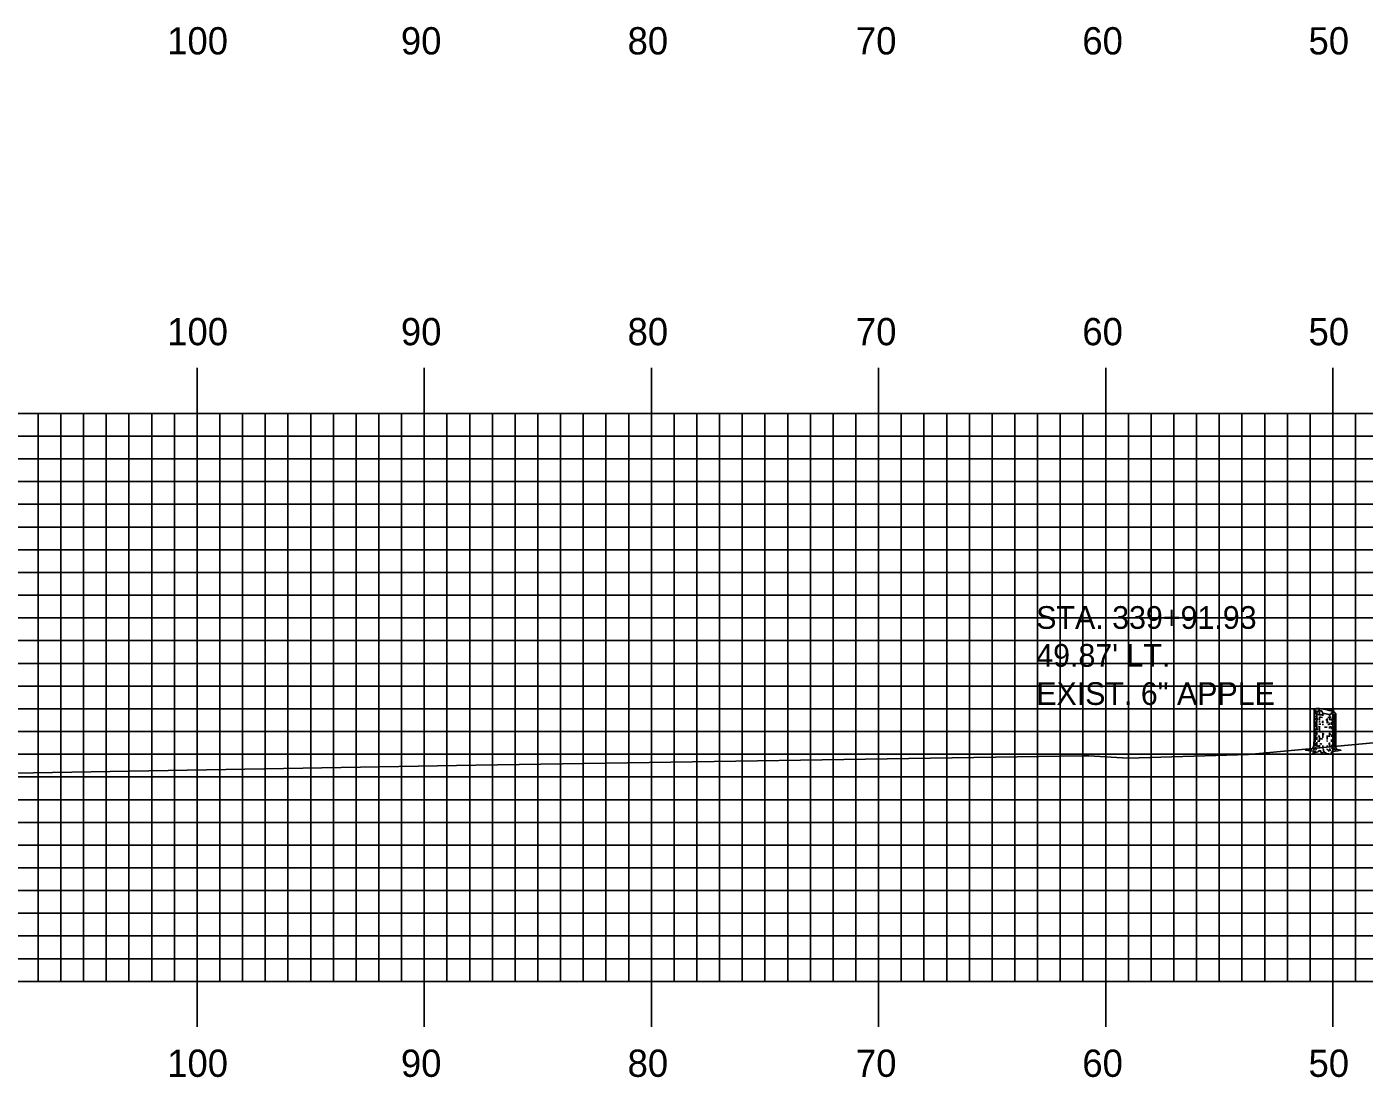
# Model space of a CAD drawing. Extents: x 1824360 to 1824703, y 442591 to 442811.
# Drawn here: x 1824417.8 to 1824476.7, y 442699.4 to 442745.7 of the extents above; entities that cross this region are included whole.
import ezdxf

# ---------------------------------------------------------------- set-up
doc = ezdxf.new("R2010")
doc.units = 0
for name, color, linetype in [('D_Text_Monospaced', 7, 'Continuous'), ('H_V ANNOTATION', 7, 'Continuous'), ('MAJOR', 7, 'Continuous'), ('MINOR', 7, 'Continuous'), ('S_Roadway_Centerline', 7, 'Continuous'), ('S_Trees_Decid_NonPay', 7, 'Continuous')]:
    doc.layers.add(name, color=color, linetype=linetype)

msp = doc.modelspace()

# ---------------------------------------------------------------- linework, layer by layer
at = {"layer": 'MAJOR'}
for p, q in [((1824425.335, 442730.669), (1824425.335, 442728.665)), ((1824435.335, 442730.669), (1824435.335, 442728.665)), ((1824445.335, 442730.669), (1824445.335, 442728.665)), ((1824455.335, 442730.669), (1824455.335, 442728.665)), ((1824465.335, 442730.669), (1824465.335, 442728.665)), ((1824475.335, 442730.669), (1824475.335, 442728.665)), ((1824385.335, 442728.665), (1824665.335, 442728.665)), ((1824385.335, 442728.665), (1824665.335, 442728.665)), ((1824425.335, 442703.665), (1824425.335, 442728.665)), ((1824435.335, 442703.665), (1824435.335, 442728.665)), ((1824445.335, 442703.665), (1824445.335, 442728.665)), ((1824455.335, 442703.665), (1824455.335, 442728.665)), ((1824465.335, 442703.665), (1824465.335, 442728.665)), ((1824475.335, 442703.665), (1824475.335, 442728.665)), ((1824385.335, 442723.665), (1824665.335, 442723.665)), ((1824385.335, 442718.665), (1824665.335, 442718.665)), ((1824385.335, 442713.665), (1824665.335, 442713.665)), ((1824385.335, 442708.665), (1824665.335, 442708.665)), ((1824385.335, 442703.665), (1824665.335, 442703.665)), ((1824385.335, 442703.665), (1824665.335, 442703.665)), ((1824425.335, 442701.661), (1824425.335, 442703.665)), ((1824435.335, 442701.661), (1824435.335, 442703.665)), ((1824445.335, 442701.661), (1824445.335, 442703.665)), ((1824455.335, 442701.661), (1824455.335, 442703.665)), ((1824465.335, 442701.661), (1824465.335, 442703.665)), ((1824475.335, 442701.661), (1824475.335, 442703.665))]:
    msp.add_line(p, q, dxfattribs=at)
at = {"layer": 'MINOR'}
for p, q in [((1824418.335, 442703.665), (1824418.335, 442728.665)), ((1824419.335, 442703.665), (1824419.335, 442728.665)), ((1824420.335, 442703.665), (1824420.335, 442728.665)), ((1824421.335, 442703.665), (1824421.335, 442728.665)), ((1824422.335, 442703.665), (1824422.335, 442728.665)), ((1824423.335, 442703.665), (1824423.335, 442728.665)), ((1824424.335, 442703.665), (1824424.335, 442728.665)), ((1824426.335, 442703.665), (1824426.335, 442728.665)), ((1824427.335, 442703.665), (1824427.335, 442728.665)), ((1824428.335, 442703.665), (1824428.335, 442728.665)), ((1824429.335, 442703.665), (1824429.335, 442728.665)), ((1824430.335, 442703.665), (1824430.335, 442728.665)), ((1824431.335, 442703.665), (1824431.335, 442728.665)), ((1824432.335, 442703.665), (1824432.335, 442728.665)), ((1824433.335, 442703.665), (1824433.335, 442728.665)), ((1824434.335, 442703.665), (1824434.335, 442728.665)), ((1824436.335, 442703.665), (1824436.335, 442728.665)), ((1824437.335, 442703.665), (1824437.335, 442728.665)), ((1824438.335, 442703.665), (1824438.335, 442728.665)), ((1824439.335, 442703.665), (1824439.335, 442728.665)), ((1824440.335, 442703.665), (1824440.335, 442728.665)), ((1824441.335, 442703.665), (1824441.335, 442728.665)), ((1824442.335, 442703.665), (1824442.335, 442728.665)), ((1824443.335, 442703.665), (1824443.335, 442728.665)), ((1824444.335, 442703.665), (1824444.335, 442728.665)), ((1824446.335, 442703.665), (1824446.335, 442728.665)), ((1824447.335, 442703.665), (1824447.335, 442728.665)), ((1824448.335, 442703.665), (1824448.335, 442728.665)), ((1824449.335, 442703.665), (1824449.335, 442728.665)), ((1824450.335, 442703.665), (1824450.335, 442728.665)), ((1824451.335, 442703.665), (1824451.335, 442728.665)), ((1824452.335, 442703.665), (1824452.335, 442728.665)), ((1824453.335, 442703.665), (1824453.335, 442728.665)), ((1824454.335, 442703.665), (1824454.335, 442728.665)), ((1824456.335, 442703.665), (1824456.335, 442728.665)), ((1824457.335, 442703.665), (1824457.335, 442728.665)), ((1824458.335, 442703.665), (1824458.335, 442728.665)), ((1824459.335, 442703.665), (1824459.335, 442728.665)), ((1824460.335, 442703.665), (1824460.335, 442728.665)), ((1824461.335, 442703.665), (1824461.335, 442728.665)), ((1824462.335, 442703.665), (1824462.335, 442728.665)), ((1824463.335, 442703.665), (1824463.335, 442728.665)), ((1824464.335, 442703.665), (1824464.335, 442728.665)), ((1824466.335, 442703.665), (1824466.335, 442728.665)), ((1824467.335, 442703.665), (1824467.335, 442728.665)), ((1824468.335, 442703.665), (1824468.335, 442728.665)), ((1824469.335, 442703.665), (1824469.335, 442728.665)), ((1824470.335, 442703.665), (1824470.335, 442728.665)), ((1824471.335, 442703.665), (1824471.335, 442728.665)), ((1824472.335, 442703.665), (1824472.335, 442728.665)), ((1824473.335, 442703.665), (1824473.335, 442728.665)), ((1824474.335, 442703.665), (1824474.335, 442728.665)), ((1824476.335, 442703.665), (1824476.335, 442728.665)), ((1824385.335, 442727.665), (1824665.335, 442727.665)), ((1824385.335, 442726.665), (1824665.335, 442726.665)), ((1824385.335, 442725.665), (1824665.335, 442725.665)), ((1824385.335, 442724.665), (1824665.335, 442724.665)), ((1824385.335, 442722.665), (1824665.335, 442722.665)), ((1824385.335, 442721.665), (1824665.335, 442721.665)), ((1824385.335, 442720.665), (1824665.335, 442720.665)), ((1824385.335, 442719.665), (1824665.335, 442719.665)), ((1824385.335, 442717.665), (1824665.335, 442717.665)), ((1824385.335, 442716.665), (1824665.335, 442716.665)), ((1824385.335, 442715.665), (1824665.335, 442715.665)), ((1824385.335, 442714.665), (1824665.335, 442714.665)), ((1824385.335, 442712.665), (1824665.335, 442712.665)), ((1824385.335, 442711.665), (1824665.335, 442711.665)), ((1824385.335, 442710.665), (1824665.335, 442710.665)), ((1824385.335, 442709.665), (1824665.335, 442709.665)), ((1824385.335, 442707.665), (1824665.335, 442707.665)), ((1824385.335, 442706.665), (1824665.335, 442706.665)), ((1824385.335, 442705.665), (1824665.335, 442705.665)), ((1824385.335, 442704.665), (1824665.335, 442704.665))]:
    msp.add_line(p, q, dxfattribs=at)
at = {"layer": 'S_Roadway_Centerline'}
msp.add_lwpolyline([(1824385.335, 442712.032), (1824402.824, 442712.451), (1824409.16, 442712.566), (1824410.669, 442712.679), (1824412.52, 442712.735), (1824413.871, 442712.78), (1824437.612, 442713.181), (1824464.293, 442713.588), (1824464.596, 442713.6), (1824466.327, 442713.494), (1824471.624, 442713.647), (1824477.578, 442714.207)], dxfattribs=at)
at = {"layer": 'S_Trees_Decid_NonPay'}
for p, q in [((1824474.564, 442715.583), (1824474.564, 442715.488)), ((1824474.564, 442715.262), (1824474.564, 442715.179)), ((1824474.564, 442715.109), (1824474.564, 442714.858)), ((1824474.632, 442715.496), (1824474.632, 442715.195)), ((1824474.632, 442715.167), (1824474.632, 442715.035)), ((1824474.632, 442715.001), (1824474.632, 442714.72)), ((1824474.751, 442715.513), (1824474.751, 442715.365)), ((1824474.751, 442715.317), (1824474.751, 442715.148)), ((1824474.898, 442715.467), (1824474.898, 442715.36)), ((1824474.898, 442715.132), (1824474.898, 442715.045)), ((1824474.898, 442715.01), (1824474.898, 442714.94)), ((1824475.078, 442715.231), (1824475.078, 442715.031)), ((1824475.195, 442715.415), (1824475.195, 442715.336)), ((1824475.195, 442715.249), (1824475.195, 442715.165)), ((1824475.195, 442715.054), (1824475.195, 442714.953)), ((1824475.282, 442715.231), (1824475.282, 442715.144)), ((1824475.282, 442715.074), (1824475.282, 442714.953)), ((1824475.353, 442715.404), (1824475.353, 442715.352)), ((1824475.353, 442715.249), (1824475.353, 442715.167)), ((1824475.353, 442715.132), (1824475.353, 442715.058)), ((1824475.353, 442715.031), (1824475.353, 442714.971)), ((1824475.395, 442715.409), (1824475.395, 442715.191)), ((1824475.395, 442715.123), (1824475.395, 442714.971)), ((1824475.422, 442715.339), (1824475.422, 442715.257)), ((1824475.422, 442715.188), (1824475.422, 442715.058)), ((1824475.422, 442715.035), (1824475.422, 442714.854)), ((1824474.564, 442714.775), (1824474.564, 442714.545)), ((1824474.564, 442714.475), (1824474.564, 442714.314)), ((1824474.632, 442714.65), (1824474.632, 442714.506)), ((1824474.632, 442714.436), (1824474.632, 442714.294)), ((1824474.751, 442714.842), (1824474.751, 442714.693)), ((1824474.751, 442714.424), (1824474.751, 442714.271)), ((1824474.898, 442714.607), (1824474.898, 442714.384)), ((1824475.078, 442714.493), (1824475.078, 442714.306)), ((1824475.195, 442714.868), (1824475.195, 442714.792)), ((1824475.195, 442714.607), (1824475.195, 442714.51)), ((1824475.282, 442714.877), (1824475.282, 442714.763)), ((1824475.282, 442714.701), (1824475.282, 442714.619)), ((1824475.282, 442714.533), (1824475.282, 442714.436)), ((1824475.353, 442714.918), (1824475.353, 442714.737)), ((1824475.353, 442714.705), (1824475.353, 442714.623)), ((1824475.353, 442714.569), (1824475.353, 442714.399)), ((1824475.353, 442714.365), (1824475.353, 442714.086)), ((1824475.395, 442714.866), (1824475.395, 442714.788)), ((1824475.395, 442714.761), (1824475.395, 442714.654)), ((1824475.395, 442714.619), (1824475.395, 442714.518)), ((1824475.395, 442714.493), (1824475.395, 442714.31)), ((1824475.422, 442714.806), (1824475.422, 442714.56)), ((1824475.422, 442714.541), (1824475.422, 442714.446)), ((1824475.424, 442714.393), (1824475.423, 442714.133)), ((1824474.564, 442714.298), (1824474.564, 442714.193)), ((1824474.564, 442714.156), (1824474.564, 442714.032)), ((1824474.631, 442713.952), (1824474.59, 442713.856)), ((1824474.632, 442714.193), (1824474.632, 442714.012)), ((1824474.751, 442714.059), (1824474.751, 442713.981)), ((1824474.898, 442714.051), (1824474.898, 442713.985)), ((1824474.938, 442713.765), (1824474.903, 442713.911)), ((1824475.078, 442714.275), (1824475.078, 442714.222)), ((1824475.078, 442714.046), (1824475.078, 442713.956)), ((1824475.195, 442714.185), (1824475.195, 442713.961)), ((1824475.282, 442714.306), (1824475.282, 442714.207)), ((1824475.282, 442714.078), (1824475.282, 442714.02)), ((1824475.353, 442714.033), (1824475.353, 442714.008)), ((1824475.393, 442713.968), (1824475.428, 442713.917)), ((1824475.395, 442714.207), (1824475.395, 442714.016)), ((1824475.475, 442713.847), (1824475.408, 442713.878)), ((1824475.422, 442714.094), (1824475.422, 442714.02))]:
    msp.add_line(p, q, dxfattribs=at)
for points in [[(1824475.463, 442715.447), (1824475.463, 442714.035), (1824475.486, 442713.886), (1824475.689, 442713.843), (1824475.549, 442713.808), (1824475.331, 442713.789), (1824475.261, 442713.746), (1824475.383, 442713.657), (1824475.051, 442713.701), (1824474.938, 442713.765), (1824474.845, 442713.705), (1824474.79, 442713.783), (1824474.798, 442713.82), (1824474.736, 442713.822), (1824474.685, 442713.765), (1824474.452, 442713.713), (1824474.58, 442713.802), (1824474.448, 442713.804), (1824474.139, 442713.841), (1824474.378, 442713.872), (1824474.456, 442713.93), (1824474.495, 442714.051), (1824474.512, 442714.405), (1824474.512, 442715.638)], [(1824474.876, 442715.472), (1824474.868, 442715.539), (1824474.843, 442715.544), (1824474.835, 442715.579), (1824474.804, 442715.564), (1824474.79, 442715.579), (1824474.765, 442715.556), (1824474.742, 442715.564), (1824474.73, 442715.613), (1824474.722, 442715.57), (1824474.691, 442715.579), (1824474.688, 442715.527)], [(1824475.368, 442715.527), (1824475.364, 442715.622), (1824475.35, 442715.595), (1824475.35, 442715.716), (1824475.329, 442715.653), (1824475.314, 442715.686), (1824475.298, 442715.63), (1824475.282, 442715.647), (1824475.263, 442715.638), (1824475.244, 442715.571)], [(1824475.346, 442715.403), (1824475.329, 442715.465), (1824475.307, 442715.453), (1824475.276, 442715.488), (1824475.242, 442715.41)], [(1824474.561, 442713.989), (1824474.553, 442713.913), (1824474.475, 442713.863)], [(1824475.086, 442713.907), (1824475.086, 442713.87), (1824475.137, 442713.839), (1824475.154, 442713.789)], [(1824475.198, 442713.913), (1824475.204, 442713.843), (1824475.267, 442713.831)], [(1824475.345, 442713.878), (1824475.302, 442713.913), (1824475.294, 442713.961)], [(1824475.424, 442713.894), (1824475.345, 442713.878), (1824475.329, 442713.835)]]:
    msp.add_lwpolyline(points, dxfattribs=at)
for centre, radius, start, end in [((1824474.53, 442715.638), 0.0179, 168.17229, 184.22782), ((1824474.536, 442715.639), 0.0237, 184.22782, 198.17229), ((1824474.53, 442715.638), 0.0179, 152.11676, 168.17229), ((1824474.545, 442715.642), 0.0336, 198.17229, 216.94859), ((1824474.535, 442715.636), 0.0237, 138.17229, 152.11676), ((1824474.543, 442715.629), 0.0336, 119.39599, 138.17229), ((1824474.593, 442715.678), 0.0935, 216.9486, 228.17229), ((1824474.572, 442715.577), 0.0935, 108.17229, 119.39599), ((1824474.745, 442715.848), 0.322, 228.17229, 250.29024), ((1824474.643, 442715.36), 0.322, 86.05435, 108.17229), ((1824475.482, 442717.905), 2.507, 250.29024, 251.52809), ((1824474.493, 442713.18), 2.507, 78.17229, 86.05435), ((1824474.493, 442713.18), 2.507, 70.29024, 78.17229), ((1824475.23, 442715.237), 0.322, 48.17229, 70.29024), ((1824474.531, 442715.491), 0.0191, 163.94846, 180), ((1824474.531, 442715.491), 0.0191, 180, 196.05154), ((1824474.536, 442715.493), 0.0252, 196.05154, 210), ((1824474.531, 442715.277), 0.0191, 163.94846, 180), ((1824474.531, 442715.277), 0.0191, 180, 196.05154), ((1824474.536, 442715.279), 0.0252, 196.05154, 210), ((1824474.531, 442715.174), 0.0191, 163.94846, 180), ((1824474.531, 442715.174), 0.0191, 180, 196.05154), ((1824474.536, 442715.176), 0.0252, 196.05154, 210), ((1824474.531, 442714.954), 0.0191, 163.94846, 180), ((1824474.531, 442714.954), 0.0191, 180, 196.05154), ((1824474.536, 442714.956), 0.0252, 196.05154, 210), ((1824474.546, 442715.498), 0.0356, 210, 228.74941), ((1824474.546, 442715.284), 0.0356, 210, 228.74941), ((1824474.546, 442715.181), 0.0356, 210, 228.74941), ((1824474.546, 442714.961), 0.0356, 210, 228.74941), ((1824474.587, 442715.545), 0.0984, 228.74941, 240), ((1824474.587, 442715.331), 0.0984, 228.74941, 240), ((1824474.587, 442715.228), 0.0984, 228.74941, 240), ((1824474.701, 442715.742), 0.326, 240, 248.32432), ((1824474.701, 442715.528), 0.326, 240, 243.57187), ((1824474.701, 442715.425), 0.326, 240, 243.24303), ((1824474.701, 442715.629), 0.326, 240.90989, 257.8036), ((1824474.701, 442715.32), 0.326, 245.15448, 257.8036), ((1824474.701, 442715.528), 0.326, 250.41675, 261.8968), ((1824474.701, 442715.425), 0.326, 251.68306, 257.8036), ((1824474.701, 442715.742), 0.326, 257.8036, 261.8968), ((1824474.987, 442717.752), 2.356, 261.8968, 263.27991), ((1824474.987, 442717.538), 2.356, 261.8968, 262.55191), ((1824474.987, 442717.33), 2.356, 263.26817, 265.63617), ((1824474.987, 442717.435), 2.356, 263.34129, 264.99462), ((1824474.987, 442717.639), 2.356, 264.24201, 267.36728), ((1824474.987, 442717.752), 2.356, 265.24001, 267.83857), ((1824474.987, 442717.435), 2.356, 266.50356, 267.83857), ((1824475.482, 442717.905), 2.507, 255.99867, 258.17229), ((1824475.482, 442717.905), 2.507, 258.17229, 264.50134), ((1824474.987, 442717.538), 2.356, 270.81188, 272.1981), ((1824474.987, 442717.435), 2.356, 272.1981, 273.97408), ((1824474.987, 442717.33), 2.356, 273.0067, 275.06467), ((1824474.987, 442717.639), 2.356, 273.14807, 276.77338), ((1824474.987, 442717.538), 2.356, 275.06468, 278.1032), ((1824474.987, 442717.33), 2.356, 277.18685, 278.1032), ((1824474.987, 442717.435), 2.356, 277.38384, 278.1032), ((1824475.273, 442715.528), 0.326, 278.1032, 279.08543), ((1824475.273, 442715.425), 0.326, 278.1032, 284.03823), ((1824475.273, 442715.32), 0.326, 278.1032, 284.03823), ((1824475.332, 442715.725), 0.322, 272.44787, 288.17229), ((1824475.273, 442715.629), 0.326, 291.95057, 300), ((1824475.273, 442715.528), 0.326, 291.95057, 300), ((1824475.273, 442715.32), 0.326, 291.95057, 300), ((1824475.403, 442715.508), 0.0935, 288.17229, 299.39599), ((1824475.387, 442715.432), 0.0984, 300, 311.25059), ((1824475.387, 442715.331), 0.0984, 300, 311.25059), ((1824475.387, 442715.123), 0.0984, 300, 311.25059), ((1824475.382, 442715.407), 0.0935, 36.9486, 48.17229), ((1824475.433, 442715.456), 0.0336, 299.39599, 318.17229), ((1824475.428, 442715.385), 0.0356, 311.25059, 330), ((1824475.428, 442715.284), 0.0356, 311.25059, 330), ((1824475.428, 442715.076), 0.0356, 311.25059, 330), ((1824475.428, 442714.961), 0.0356, 311.25059, 330), ((1824475.43, 442715.443), 0.0336, 18.17229, 36.94859), ((1824475.44, 442715.45), 0.0237, 318.17229, 332.11676), ((1824475.437, 442715.379), 0.0252, 330, 343.94846), ((1824475.437, 442715.279), 0.0252, 330, 343.94846), ((1824475.437, 442715.071), 0.0252, 330, 343.94846), ((1824475.437, 442714.956), 0.0252, 330, 343.94846), ((1824475.445, 442715.447), 0.0179, 332.11676, 348.17229), ((1824475.439, 442715.446), 0.0237, 4.22782, 18.17229), ((1824475.443, 442715.378), 0.0191, 360, 6.11276), ((1824475.443, 442715.378), 0.0191, 343.94846, 360), ((1824475.443, 442715.277), 0.0191, 360, 6.11276), ((1824475.443, 442715.277), 0.0191, 343.94846, 360), ((1824475.443, 442715.174), 0.0191, 360, 6.11276), ((1824475.443, 442715.174), 0.0191, 343.94846, 360), ((1824475.443, 442715.069), 0.0191, 360, 6.11276), ((1824475.443, 442715.069), 0.0191, 343.94846, 360), ((1824475.443, 442714.954), 0.0191, 360, 6.11276), ((1824475.443, 442714.954), 0.0191, 343.94846, 360), ((1824475.445, 442715.447), 0.0179, 348.17229, 4.22783), ((1824474.528, 442714.739), 0.0191, 163.94846, 180), ((1824474.531, 442714.839), 0.0191, 163.94846, 180), ((1824474.531, 442714.839), 0.0191, 180, 196.05154), ((1824474.531, 442714.634), 0.0191, 163.94846, 180), ((1824474.531, 442714.634), 0.0191, 180, 196.05154), ((1824474.536, 442714.636), 0.0252, 196.05154, 210), ((1824474.537, 442714.841), 0.0252, 196.05154, 210), ((1824474.546, 442714.846), 0.0356, 210, 228.74941), ((1824474.546, 442714.641), 0.0356, 210, 228.74941), ((1824474.587, 442715.008), 0.0984, 228.74941, 240), ((1824474.587, 442714.689), 0.0984, 228.74941, 240), ((1824474.588, 442714.894), 0.0984, 228.74941, 240), ((1824474.698, 442714.99), 0.326, 240, 256.90786), ((1824474.701, 442715.205), 0.326, 240, 245.15448), ((1824474.701, 442715.091), 0.326, 240, 247.86558), ((1824474.701, 442714.886), 0.326, 240, 245.15448), ((1824474.701, 442714.795), 0.326, 241.93896, 253.9183), ((1824474.701, 442715.091), 0.326, 257.66994, 261.8968), ((1824474.988, 442717.101), 2.356, 261.8968, 262.86151), ((1824474.987, 442716.805), 2.356, 262.58433, 264.48651), ((1824474.987, 442717.215), 2.356, 262.65877, 264.79114), ((1824474.985, 442717.001), 2.356, 264.3443, 266.85288), ((1824474.987, 442716.896), 2.356, 267.83857, 269.00542), ((1824474.987, 442717.215), 2.356, 269.55779, 270), ((1824474.987, 442717.215), 2.356, 270, 272.414), ((1824474.987, 442716.805), 2.356, 272.1981, 275.27259), ((1824474.985, 442717.001), 2.356, 274.97344, 277.24554), ((1824474.987, 442717.215), 2.356, 275.06467, 277.18685), ((1824474.987, 442716.896), 2.356, 275.06467, 276.42799), ((1824475.273, 442715.205), 0.326, 284.03823, 300), ((1824475.274, 442715.091), 0.326, 283.90364, 291.80982), ((1824475.273, 442714.886), 0.326, 284.03823, 291.95057), ((1824475.273, 442714.682), 0.326, 284.03823, 291.95057), ((1824475.271, 442714.99), 0.326, 292.40493, 300), ((1824475.274, 442715.091), 0.326, 297.00583, 300), ((1824475.273, 442714.886), 0.326, 297.15252, 300), ((1824475.385, 442714.793), 0.0984, 300, 311.25059), ((1824475.387, 442715.008), 0.0984, 300, 311.25059), ((1824475.387, 442714.689), 0.0984, 300, 311.25059), ((1824475.388, 442714.894), 0.0984, 300, 311.25059), ((1824475.426, 442714.746), 0.0356, 311.25059, 330), ((1824475.428, 442714.641), 0.0356, 311.25059, 330), ((1824475.429, 442714.846), 0.0356, 311.25059, 330), ((1824475.435, 442714.741), 0.0252, 330, 343.94846), ((1824475.441, 442714.739), 0.0191, 343.94846, 360), ((1824475.437, 442714.636), 0.0252, 330, 343.94846), ((1824475.438, 442714.841), 0.0252, 330, 343.94846), ((1824475.441, 442714.739), 0.0191, 0, 6.11277), ((1824475.444, 442714.839), 0.0191, 343.94846, 360), ((1824475.443, 442714.634), 0.0191, 360, 6.11276), ((1824475.443, 442714.634), 0.0191, 343.94846, 360), ((1824475.443, 442714.544), 0.0191, 360, 6.11276), ((1824475.444, 442714.839), 0.0191, 0, 6.11277), ((1824474.516, 442714.095), 0.0191, 163.94846, 180), ((1824474.516, 442714.095), 0.0191, 180, 196.05154), ((1824474.522, 442714.096), 0.0252, 196.05154, 210), ((1824474.531, 442714.101), 0.0356, 210, 228.74941), ((1824474.522, 442714.205), 0.0191, 163.94846, 180), ((1824474.522, 442714.205), 0.0191, 180, 196.05154), ((1824474.528, 442714.207), 0.0252, 196.05154, 210), ((1824474.537, 442714.212), 0.0356, 210, 228.74941), ((1824474.527, 442714.315), 0.0191, 163.94846, 180), ((1824474.527, 442714.315), 0.0191, 180, 196.05154), ((1824474.532, 442714.317), 0.0252, 196.05154, 210), ((1824474.572, 442714.149), 0.0984, 228.74941, 240), ((1824474.541, 442714.322), 0.0356, 210, 228.74941), ((1824474.578, 442714.259), 0.0984, 228.74941, 240), ((1824474.583, 442714.37), 0.0984, 228.74941, 240), ((1824474.686, 442714.346), 0.326, 240, 247.9161), ((1824474.692, 442714.456), 0.326, 240, 241.90969), ((1824474.697, 442714.567), 0.326, 240, 245.93749), ((1824474.686, 442714.346), 0.326, 260.38342, 261.8968), ((1824474.973, 442716.356), 2.356, 261.8968, 263.53328), ((1824474.983, 442716.577), 2.356, 262.22258, 264.4852), ((1824474.987, 442716.692), 2.356, 264.24201, 267.46903), ((1824474.978, 442716.466), 2.356, 264.90887, 266.81578), ((1824474.978, 442716.466), 2.356, 274.18643, 275.28293), ((1824474.973, 442716.356), 2.356, 274.55512, 275.4167), ((1824474.983, 442716.577), 2.356, 277.28629, 278.1032), ((1824474.973, 442716.356), 2.356, 277.54032, 278.1032), ((1824475.259, 442714.346), 0.326, 278.1032, 294.70938), ((1824475.269, 442714.567), 0.326, 278.1032, 284.77414), ((1824475.264, 442714.456), 0.326, 293.6544, 300), ((1824475.373, 442714.149), 0.0984, 300, 311.25059), ((1824475.383, 442714.37), 0.0984, 300, 311.25059), ((1824475.414, 442714.101), 0.0356, 311.25059, 330), ((1824475.423, 442714.096), 0.0252, 330, 343.94846), ((1824475.429, 442714.095), 0.0191, 343.94846, 360), ((1824475.424, 442714.322), 0.0356, 311.25059, 330), ((1824475.429, 442714.095), 0.0191, 0, 6.11277), ((1824475.433, 442714.317), 0.0252, 330, 343.94846), ((1824475.439, 442714.315), 0.0191, 360, 6.11276), ((1824475.439, 442714.315), 0.0191, 343.94846, 360)]:
    msp.add_arc(centre, radius, start, end, dxfattribs=at)

# ---------------------------------------------------------------- texts
at = {"layer": 'D_Text_Monospaced'}
for s, height, p in [('STA. 339+91.93', 0.99996, (1824462.276, 442719.183)), ("49.87' LT.", 1, (1824462.276, 442717.515)), ('EXIST. 6" APPLE', 0.99996, (1824462.276, 442715.835))]:
    msp.add_text(s, height=height, dxfattribs=at).set_placement(p)
at = {"layer": 'H_V ANNOTATION'}
for s, p in [('100', (1824424.018, 442744.465)), ('90', (1824434.307, 442744.465)), ('80', (1824444.286, 442744.465)), ('70', (1824454.339, 442744.465)), ('60', (1824464.307, 442744.465)), ('50', (1824474.264, 442744.465)), ('100', (1824424.018, 442731.665)), ('90', (1824434.307, 442731.665)), ('80', (1824444.286, 442731.665)), ('70', (1824454.339, 442731.665)), ('60', (1824464.307, 442731.665)), ('50', (1824474.264, 442731.665)), ('100', (1824424.018, 442699.465)), ('90', (1824434.307, 442699.465)), ('80', (1824444.286, 442699.465)), ('70', (1824454.339, 442699.465)), ('60', (1824464.307, 442699.465)), ('50', (1824474.264, 442699.465))]:
    msp.add_text(s, height=1.2, dxfattribs=at).set_placement(p)

doc.saveas('drawing.dxf')
